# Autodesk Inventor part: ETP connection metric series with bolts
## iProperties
Author: Administrator
Shininess: 60.0
PropertySet Name: _Private Model Information
Created: 2001-04
Part Number: ETP connection metric series with bolts
Material: Steel, Mild
Document SubType Name: Modeling
Designer: Administrator
Control State: 0
Master: False
Checked Out: False
PropertySet Name: Design Tracking Control
Density: 0.0
Volumn: 0.0
Area: 0.0
PropertySet Name: Model Information
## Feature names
1. Revolution1
2. Fillet1
3. Chamfer1
4. Extrusion3
5. Extrusion4
6. Chamfer3
7. Extrusion5
8. Extrusion6
9. Chamfer4
10. Circular Pattern2
